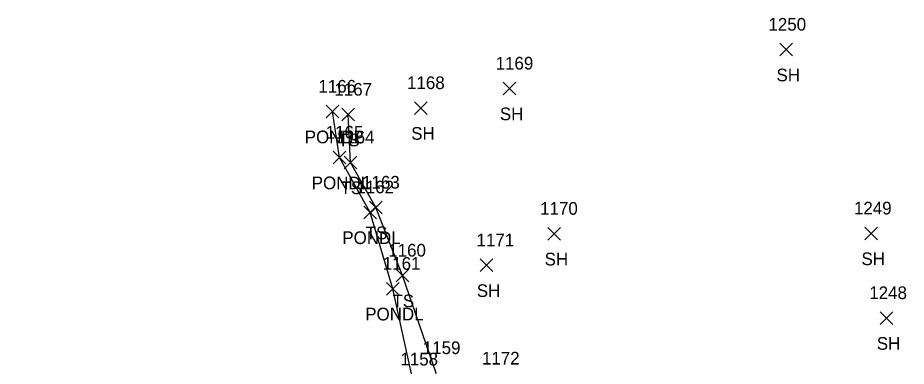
# Model space of a CAD drawing. Extents: x 1497084 to 1499861, y 734741 to 735567.
# Drawn here: x 1498306.3 to 1498446.6, y 735362.1 to 735417.1 of the extents above; entities that cross this region are included whole.
import ezdxf

# ---------------------------------------------------------------- set-up
doc = ezdxf.new("R2010")
doc.units = 0
for name, color, linetype in [('L_A', 7, 'Continuous'), ('L_I', 7, 'Continuous'), ('L_TIC', 7, 'Continuous'), ('LAWE', 7, 'Continuous'), ('LELB', 7, 'Continuous')]:
    doc.layers.add(name, color=color, linetype=linetype)

msp = doc.modelspace()

# ---------------------------------------------------------------- linework, layer by layer
at = {"layer": 'L_TIC'}
for points in [[(1498426.63, 735411.09), (1498428.63, 735413.09)], [(1498428.63, 735411.09), (1498426.63, 735413.09)], [(1498382.94, 735404.95), (1498384.94, 735406.95)], [(1498384.94, 735404.95), (1498382.94, 735406.95)], [(1498368.94, 735401.87), (1498370.94, 735403.87)], [(1498370.94, 735401.87), (1498368.94, 735403.87)], [(1498355, 735401.31), (1498357, 735403.31)], [(1498357, 735401.31), (1498355, 735403.31)], [(1498357.46, 735400.83), (1498359.46, 735402.83)], [(1498359.46, 735400.83), (1498357.46, 735402.83)], [(1498356.1, 735394.06), (1498358.1, 735396.06)], [(1498358.1, 735394.06), (1498356.1, 735396.06)], [(1498357.85, 735393.29), (1498359.85, 735395.29)], [(1498359.85, 735393.29), (1498357.85, 735395.29)], [(1498361.84, 735386.16), (1498363.84, 735388.16)], [(1498363.84, 735386.16), (1498361.84, 735388.16)], [(1498360.93, 735385.41), (1498362.93, 735387.41)], [(1498362.93, 735385.41), (1498360.93, 735387.41)], [(1498390.01, 735382.03), (1498392.01, 735384.03)], [(1498392.01, 735382.03), (1498390.01, 735384.03)], [(1498440.06, 735382.08), (1498442.06, 735384.08)], [(1498442.06, 735382.08), (1498440.06, 735384.08)], [(1498379.3, 735377.05), (1498381.3, 735379.05)], [(1498381.3, 735377.05), (1498379.3, 735379.05)], [(1498366.06, 735375.43), (1498368.06, 735377.43)], [(1498368.06, 735375.43), (1498366.06, 735377.43)], [(1498364.54, 735373.35), (1498366.54, 735375.35)], [(1498366.54, 735373.35), (1498364.54, 735375.35)], [(1498442.47, 735368.72), (1498444.47, 735370.72)], [(1498444.47, 735368.72), (1498442.47, 735370.72)]]:
    msp.add_lwpolyline(points, dxfattribs=at)
at = {"layer": 'LAWE'}
msp.add_lwpolyline([(1498275.46, 735378.17), (1498275.69, 735363.91), (1498285.13, 735344.96), (1498291.05, 735337.01), (1498299.89, 735330.14), (1498310.47, 735326.85), (1498319.02, 735327.27), (1498323.8, 735327.85), (1498325.54, 735326.28), (1498335.98, 735328.26), (1498338.67, 735333.84), (1498347.71, 735340.62), (1498357.75, 735341.88), (1498365.93, 735349.29), (1498368.84, 735359.24), (1498365.54, 735374.35), (1498361.93, 735386.41), (1498357.1, 735395.06), (1498356, 735402.31)], dxfattribs=at)
at = {"layer": 'LELB'}
msp.add_lwpolyline([(1498337.56, 735327.03), (1498338.52, 735333.48), (1498348.72, 735338.62), (1498358.22, 735339.73), (1498367.4, 735347.05), (1498372.39, 735361.04), (1498367.06, 735376.43), (1498362.84, 735387.16), (1498358.85, 735394.29), (1498358.46, 735401.83)], dxfattribs=at)

# ---------------------------------------------------------------- texts
at = {"layer": 'L_A'}
for s, p in [('SH', (1498426.12, 735407.09)), ('SH', (1498382.43, 735400.95)), ('PONDL', (1498351.62, 735397.31)), ('SH', (1498368.43, 735397.87)), ('TS', (1498356.87, 735396.83)), ('PONDL', (1498352.72, 735390.06)), ('TS', (1498357.26, 735389.29)), ('TS', (1498361.25, 735382.16)), ('PONDL', (1498357.55, 735381.41)), ('SH', (1498389.5, 735378.03)), ('SH', (1498439.54, 735378.08)), ('SH', (1498378.79, 735373.05)), ('TS', (1498365.47, 735371.43)), ('PONDL', (1498361.17, 735369.35)), ('SH', (1498441.96, 735364.72))]:
    msp.add_text(s, height=2, dxfattribs=at).set_placement(p)
at = {"layer": 'L_I'}
for s, p in [('1250', (1498424.85, 735415.09)), ('1169', (1498381.76, 735408.95)), ('1168', (1498367.77, 735405.87)), ('1166', (1498353.77, 735405.31)), ('1167', (1498356.29, 735404.83)), ('1165', (1498354.93, 735398.06)), ('1164', (1498356.68, 735397.29)), ('1163', (1498360.67, 735390.16)), ('1162', (1498359.76, 735389.41)), ('1170', (1498388.79, 735386.03)), ('1249', (1498438.35, 735386.08)), ('1171', (1498378.74, 735381.05)), ('1160', (1498364.8, 735379.43)), ('1161', (1498363.94, 735377.35)), ('1248', (1498440.77, 735372.72)), ('1159', (1498370.26, 735364.04)), ('1159', (1498370.26, 735364.04)), ('1158', (1498366.72, 735362.24)), ('1172', (1498379.6, 735362.39))]:
    msp.add_text(s, height=2, dxfattribs=at).set_placement(p)

doc.saveas('drawing.dxf')
